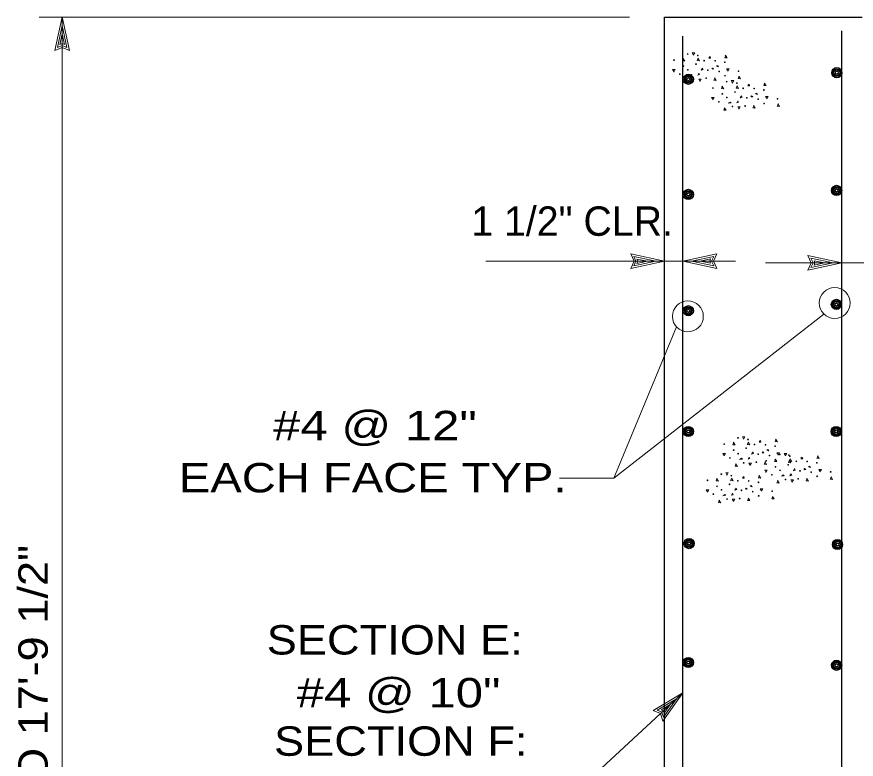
# Model space of a CAD drawing. Extents: x -28.1 to 13.9, y -16.1 to 13.9.
# Drawn here: x -10.389 to -6.817, y -5.87 to -2.71 of the extents above; entities that cross this region are included whole.
import ezdxf
from ezdxf.enums import TextEntityAlignment as Align

# ---------------------------------------------------------------- set-up
doc = ezdxf.new("R2010")
doc.units = 0
doc.header["$LTSCALE"] = 0.05
doc.layers.add('1', color=7, linetype='Continuous', lineweight=13)
doc.layers.add('2', color=7, linetype='Continuous', lineweight=13)

msp = doc.modelspace()

# ---------------------------------------------------------------- linework, layer by layer
at = {"layer": '1'}
for p, q in [((-7.78204, -2.71131), (-10.29304, -2.71131)), ((-10.19604, -2.71031), (-10.22704, -2.85431)), ((-10.19604, -2.71031), (-10.16504, -2.85431)), ((-10.19604, -2.74731), (-10.21604, -2.84131)), ((-10.19604, -2.74731), (-10.17604, -2.84131)), ((-10.19604, -2.78331), (-10.20504, -2.82831)), ((-10.19604, -2.78331), (-10.18604, -2.82831)), ((-10.19604, -2.83231), (-10.21604, -2.84131)), ((-10.19604, -2.82431), (-10.20504, -2.82831)), ((-10.18604, -2.82831), (-10.19604, -2.82431)), ((-10.17604, -2.84131), (-10.19604, -2.83231)), ((-7.63204, -3.75031), (-7.77604, -3.71931)), ((-7.63204, -3.75031), (-7.77604, -3.78131)), ((-7.66904, -3.75031), (-7.76304, -3.73031)), ((-7.75404, -3.75031), (-7.76304, -3.73031)), ((-7.66904, -3.75031), (-7.76304, -3.77031)), ((-7.76304, -3.77031), (-7.75404, -3.75031)), ((-7.70504, -3.75031), (-7.75004, -3.74131)), ((-7.74604, -3.75031), (-7.75004, -3.74131)), ((-7.70504, -3.75031), (-7.75004, -3.76031)), ((-7.75004, -3.76031), (-7.74604, -3.75031)), ((-7.55404, -3.75031), (-7.41004, -3.71931)), ((-7.55404, -3.75031), (-7.41004, -3.78131)), ((-7.51704, -3.75031), (-7.42304, -3.73031)), ((-7.51704, -3.75031), (-7.42304, -3.77031)), ((-7.48104, -3.75031), (-7.43604, -3.74031)), ((-7.48104, -3.75031), (-7.43604, -3.75931)), ((-7.43604, -3.74031), (-7.44004, -3.75031)), ((-7.44004, -3.75031), (-7.43604, -3.75931)), ((-7.42304, -3.73031), (-7.43204, -3.75031)), ((-7.43204, -3.75031), (-7.42304, -3.77031)), ((-6.87804, -3.75731), (-7.02204, -3.72631)), ((-6.91504, -3.75731), (-7.00904, -3.73731)), ((-7.00004, -3.75731), (-7.00904, -3.73731)), ((-6.95104, -3.75731), (-6.99604, -3.74831)), ((-6.99204, -3.75731), (-6.99604, -3.74831)), ((-6.87804, -3.75731), (-7.02204, -3.78831)), ((-6.91504, -3.75731), (-7.00904, -3.77731)), ((-7.00904, -3.77731), (-7.00004, -3.75731)), ((-6.95104, -3.75731), (-6.99604, -3.76731)), ((-6.99604, -3.76731), (-6.99204, -3.75731)), ((-7.84804, -4.67431), (-6.95404, -3.97531)), ((-7.55404, -5.58731), (-7.68104, -5.66231)), ((-7.58104, -5.61231), (-7.66404, -5.66131)), ((-7.60804, -5.63731), (-7.64704, -5.66031)), ((-7.58104, -5.61231), (-7.63704, -5.69131)), ((-7.60804, -5.63731), (-7.63404, -5.67431)), ((-7.64404, -5.67031), (-7.66404, -5.66131)), ((-7.63804, -5.66431), (-7.64704, -5.66031)), ((-7.63704, -5.69131), (-7.64404, -5.67031)), ((-7.63404, -5.67431), (-7.63804, -5.66431))]:
    msp.add_line(p, q, dxfattribs=at)
at = {"layer": '1', "lineweight": 25}
for p, q in [((-7.63204, -10.78531), (-7.63204, -2.71131)), ((-7.63204, -2.71131), (-6.79104, -2.71131)), ((-6.87804, -10.71531), (-6.87804, -2.77031)), ((-7.55404, -10.70931), (-7.55404, -2.79231))]:
    msp.add_line(p, q, dxfattribs=at)
at = {"layer": '1'}
for points in [[(-10.19604, -11.70431), (-10.19604, -9.90431), (-10.19604, -2.71031)], [(-10.16504, -2.85431), (-10.19604, -2.84031), (-10.22704, -2.85431)], [(-8.39304, -3.75031), (-7.63204, -3.75031), (-7.55404, -3.75031), (-7.33004, -3.75031)], [(-7.77604, -3.78131), (-7.76204, -3.75031), (-7.77604, -3.71931)], [(-7.41004, -3.71931), (-7.42404, -3.75031), (-7.41004, -3.78131)], [(-7.02204, -3.78831), (-7.00804, -3.75731), (-7.02204, -3.72631)], [(-7.20204, -3.75731), (-6.87804, -3.75731), (-6.79104, -3.75731), (-6.26604, -3.75731)], [(-8.07904, -4.67431), (-7.84804, -4.67431), (-7.58204, -4.02931)], [(-8.29204, -6.04931), (-8.05404, -6.04931), (-7.55404, -5.58731), (-7.63904, -5.70731)], [(-7.63904, -5.70731), (-7.64904, -5.67531), (-7.68104, -5.66231)]]:
    msp.add_lwpolyline(points, dxfattribs=at)
at = {"layer": '1', "lineweight": 25}
for centre, radius in [((-6.89899, -2.94823), 0.02168), ((-7.53099, -2.97623), 0.02168), ((-7.53099, -2.97623), 0.01681), ((-7.53099, -2.97623), 0.01233), ((-6.89899, -2.94823), 0.01681), ((-6.89899, -2.94823), 0.01233), ((-6.89899, -2.94823), 0.00623), ((-7.53099, -2.97623), 0.00623), ((-6.89999, -3.44923), 0.02168), ((-7.53099, -3.46623), 0.02168), ((-7.53099, -3.46623), 0.01681), ((-7.53099, -3.46623), 0.01233), ((-7.53099, -3.46623), 0.00623), ((-6.89999, -3.44923), 0.01681), ((-6.89999, -3.44923), 0.01233), ((-6.89999, -3.44923), 0.00623), ((-6.90099, -3.93423), 0.02168), ((-6.90099, -3.93423), 0.01681), ((-6.90099, -3.93423), 0.01233), ((-6.90099, -3.93423), 0.00623), ((-7.53099, -3.96123), 0.02168), ((-7.53099, -3.96123), 0.01681), ((-7.53099, -3.96123), 0.01233), ((-7.53099, -3.96123), 0.00623), ((-7.53099, -4.47523), 0.02168), ((-7.53099, -4.47523), 0.01681), ((-7.53099, -4.47523), 0.01233), ((-6.90199, -4.47523), 0.02168), ((-6.90199, -4.47523), 0.01681), ((-6.90199, -4.47523), 0.01233), ((-7.53099, -4.47523), 0.00623), ((-6.90199, -4.47523), 0.00623), ((-7.52799, -4.95223), 0.02168), ((-7.52799, -4.95223), 0.01681), ((-7.52799, -4.95223), 0.01233), ((-7.52799, -4.95223), 0.00623), ((-6.89599, -4.95623), 0.02168), ((-6.89599, -4.95623), 0.01681), ((-6.89599, -4.95623), 0.01233), ((-6.89599, -4.95623), 0.00623), ((-7.53099, -5.45823), 0.02168), ((-7.53099, -5.45823), 0.01681), ((-7.53099, -5.45823), 0.01233), ((-7.53099, -5.45823), 0.00623), ((-6.89999, -5.47023), 0.02168), ((-6.89999, -5.47023), 0.01681), ((-6.89999, -5.47023), 0.01233), ((-6.89999, -5.47023), 0.00623)]:
    msp.add_circle(centre, radius, dxfattribs=at)
at = {"layer": '1'}
for centre in [(-6.90804, -3.92831), (-7.53304, -3.98531)]:
    msp.add_circle(centre, 0.0658, dxfattribs=at)
at = {"layer": '2'}
for p, q in [((-7.44404, -2.88431), (-7.43804, -2.87931)), ((-7.27804, -3.00231), (-7.27204, -2.99731)), ((-7.23004, -4.51831), (-7.22404, -4.51331)), ((-7.05204, -4.58931), (-7.04604, -4.58431)), ((-7.30104, -4.67231), (-7.29504, -4.66731))]:
    msp.add_line(p, q, dxfattribs=at)
for points in [[(-7.55104, -2.88731), (-7.55604, -2.89731), (-7.54604, -2.89831), (-7.55404, -2.88731)], [(-7.51004, -2.87231), (-7.51504, -2.86331), (-7.50404, -2.86331), (-7.51004, -2.87431)], [(-7.48904, -2.88631), (-7.49404, -2.89631), (-7.48304, -2.89731), (-7.49104, -2.88631)], [(-7.43804, -2.87931), (-7.43604, -2.88631), (-7.44404, -2.88631)], [(-7.37104, -2.87431), (-7.37604, -2.88431), (-7.36604, -2.88531), (-7.37404, -2.87431)], [(-7.43104, -2.93231), (-7.42804, -2.92831), (-7.42304, -2.93231), (-7.43004, -2.93331)], [(-7.41104, -2.91931), (-7.40604, -2.91731), (-7.40304, -2.92331), (-7.41104, -2.92031)], [(-7.59304, -2.94331), (-7.59804, -2.93531), (-7.58704, -2.93531), (-7.59304, -2.94531)], [(-7.52404, -2.95831), (-7.51904, -2.95531), (-7.51504, -2.95831), (-7.52704, -2.96031)], [(-7.36304, -2.93931), (-7.36804, -2.93131), (-7.35704, -2.93131), (-7.36304, -2.94131)], [(-7.31404, -2.96331), (-7.31904, -2.97331), (-7.30904, -2.97431), (-7.31604, -2.96331)], [(-7.54104, -2.97931), (-7.54604, -2.98931), (-7.53604, -2.99031), (-7.54404, -2.97931)], [(-7.48204, -2.98431), (-7.48704, -2.97531), (-7.47604, -2.97531), (-7.48204, -2.98531)], [(-7.41704, -2.97031), (-7.42204, -2.98031), (-7.41204, -2.98131), (-7.42004, -2.97031)], [(-7.34404, -2.99031), (-7.34904, -2.98131), (-7.33804, -2.98131), (-7.34404, -2.99231)], [(-7.27204, -2.99731), (-7.27004, -3.00431), (-7.27804, -3.00431)], [(-7.20504, -2.99231), (-7.21004, -3.00231), (-7.20004, -3.00331), (-7.20804, -2.99231)], [(-7.38504, -3.00531), (-7.39004, -3.01531), (-7.38004, -3.01631), (-7.38804, -3.00531)], [(-7.32304, -3.00431), (-7.32804, -3.01431), (-7.31704, -3.01531), (-7.32504, -3.00431)], [(-7.24504, -3.03731), (-7.24004, -3.03531), (-7.23704, -3.04131), (-7.24504, -3.03831)], [(-7.42704, -3.06131), (-7.43204, -3.05331), (-7.42104, -3.05331), (-7.42704, -3.06331)], [(-7.26504, -3.05031), (-7.26204, -3.04631), (-7.25704, -3.05031), (-7.26404, -3.05131)], [(-7.19704, -3.05731), (-7.20204, -3.04931), (-7.19104, -3.04931), (-7.19704, -3.05931)], [(-7.37504, -3.09731), (-7.38004, -3.10731), (-7.37004, -3.10831), (-7.37804, -3.09731)], [(-7.35804, -3.07631), (-7.35304, -3.07331), (-7.34904, -3.07631), (-7.36104, -3.07831)], [(-7.31604, -3.10231), (-7.32104, -3.09331), (-7.31004, -3.09331), (-7.31604, -3.10331)], [(-7.25104, -3.08831), (-7.25604, -3.09831), (-7.24604, -3.09931), (-7.25404, -3.08831)], [(-7.14804, -3.08131), (-7.15304, -3.09131), (-7.14304, -3.09231), (-7.15004, -3.08131)], [(-7.29604, -4.50631), (-7.30104, -4.49731), (-7.29004, -4.49731), (-7.29604, -4.50831)], [(-7.33704, -4.52131), (-7.34204, -4.53131), (-7.33204, -4.53231), (-7.34004, -4.52131)], [(-7.27504, -4.52031), (-7.28004, -4.53031), (-7.26904, -4.53131), (-7.27704, -4.52031)], [(-7.22404, -4.51331), (-7.22204, -4.52031), (-7.23004, -4.52031)], [(-7.15704, -4.50831), (-7.16204, -4.51831), (-7.15204, -4.51931), (-7.16004, -4.50831)], [(-7.37904, -4.57731), (-7.38404, -4.56931), (-7.37304, -4.56931), (-7.37904, -4.57931)], [(-7.21704, -4.56631), (-7.21404, -4.56231), (-7.20904, -4.56631), (-7.21604, -4.56731)], [(-7.19704, -4.55331), (-7.19204, -4.55131), (-7.18904, -4.55731), (-7.19704, -4.55431)], [(-7.14904, -4.57331), (-7.15404, -4.56531), (-7.14304, -4.56531), (-7.14904, -4.57531)], [(-7.11804, -4.57731), (-7.12304, -4.56831), (-7.11204, -4.56831), (-7.11804, -4.57931)], [(-7.31004, -4.59231), (-7.30504, -4.58931), (-7.30104, -4.59231), (-7.31304, -4.59431)], [(-7.20304, -4.60431), (-7.20804, -4.61431), (-7.19804, -4.61531), (-7.20604, -4.60431)], [(-7.15904, -4.59231), (-7.16404, -4.60231), (-7.15404, -4.60331), (-7.16204, -4.59231)], [(-7.10004, -4.59731), (-7.10504, -4.60731), (-7.09504, -4.60831), (-7.10204, -4.59731)], [(-7.09704, -4.59131), (-7.10204, -4.60131), (-7.09104, -4.60231), (-7.09904, -4.59131)], [(-7.04604, -4.58431), (-7.04404, -4.59131), (-7.05204, -4.59131)], [(-6.97904, -4.57931), (-6.98404, -4.58931), (-6.97404, -4.59031), (-6.98204, -4.57931)], [(-7.32704, -4.61331), (-7.33204, -4.62331), (-7.32204, -4.62431), (-7.33004, -4.61331)], [(-7.26804, -4.61831), (-7.27304, -4.60931), (-7.26204, -4.60931), (-7.26804, -4.61931)], [(-7.20104, -4.64831), (-7.20604, -4.64031), (-7.19504, -4.64031), (-7.20104, -4.65031)], [(-7.03904, -4.63731), (-7.03604, -4.63331), (-7.03104, -4.63731), (-7.03804, -4.63831)], [(-7.01904, -4.62431), (-7.01404, -4.62231), (-7.01104, -4.62831), (-7.01904, -4.62531)], [(-6.97104, -4.64431), (-6.97604, -4.63631), (-6.96504, -4.63631), (-6.97104, -4.64631)], [(-7.40804, -4.67531), (-7.41304, -4.68531), (-7.40304, -4.68631), (-7.41104, -4.67531)], [(-7.36704, -4.66031), (-7.37204, -4.65131), (-7.36104, -4.65131), (-7.36704, -4.66231)], [(-7.34604, -4.67431), (-7.35104, -4.68431), (-7.34004, -4.68531), (-7.34804, -4.67431)], [(-7.29504, -4.66731), (-7.29304, -4.67431), (-7.30104, -4.67431)], [(-7.22804, -4.66231), (-7.23304, -4.67231), (-7.22304, -4.67331), (-7.23104, -4.66231)], [(-7.13204, -4.66331), (-7.12704, -4.66031), (-7.12304, -4.66331), (-7.13504, -4.66531)], [(-7.02504, -4.67531), (-7.03004, -4.68531), (-7.02004, -4.68631), (-7.02804, -4.67531)], [(-6.92204, -4.66831), (-6.92704, -4.67831), (-6.91704, -4.67931), (-6.92404, -4.66831)], [(-7.26804, -4.70731), (-7.26304, -4.70531), (-7.26004, -4.71131), (-7.26804, -4.70831)], [(-7.14904, -4.68431), (-7.15404, -4.69431), (-7.14404, -4.69531), (-7.15204, -4.68431)], [(-7.09004, -4.68931), (-7.09504, -4.68031), (-7.08404, -4.68031), (-7.09004, -4.69031)], [(-7.45004, -4.73131), (-7.45504, -4.72331), (-7.44404, -4.72331), (-7.45004, -4.73331)], [(-7.38104, -4.74631), (-7.37604, -4.74331), (-7.37204, -4.74631), (-7.38404, -4.74831)], [(-7.28804, -4.72031), (-7.28504, -4.71631), (-7.28004, -4.72031), (-7.28704, -4.72131)], [(-7.22004, -4.72731), (-7.22504, -4.71931), (-7.21404, -4.71931), (-7.22004, -4.72931)], [(-7.39804, -4.76731), (-7.40304, -4.77731), (-7.39304, -4.77831), (-7.40104, -4.76731)], [(-7.33904, -4.77231), (-7.34404, -4.76331), (-7.33304, -4.76331), (-7.33904, -4.77331)], [(-7.27404, -4.75831), (-7.27904, -4.76831), (-7.26904, -4.76931), (-7.27704, -4.75831)], [(-7.17104, -4.75131), (-7.17604, -4.76131), (-7.16604, -4.76231), (-7.17304, -4.75131)]]:
    msp.add_lwpolyline(points, dxfattribs=at)
for points in [[(-7.47604, -2.93731), (-7.47104, -2.92831), (-7.46804, -2.93431)], [(-7.49104, -2.95831), (-7.48604, -2.95031), (-7.48304, -2.95631)], [(-7.32504, -3.07631), (-7.32004, -3.06831), (-7.31704, -3.07431)], [(-7.31004, -3.05531), (-7.30504, -3.04631), (-7.30204, -3.05231)], [(-7.26204, -4.57131), (-7.25704, -4.56231), (-7.25404, -4.56831)], [(-7.27704, -4.59231), (-7.27204, -4.58431), (-7.26904, -4.59031)], [(-7.08404, -4.64231), (-7.07904, -4.63331), (-7.07604, -4.63931)], [(-7.09904, -4.66331), (-7.09404, -4.65531), (-7.09104, -4.66131)], [(-7.34804, -4.74631), (-7.34304, -4.73831), (-7.34004, -4.74431)], [(-7.33304, -4.72531), (-7.32804, -4.71631), (-7.32504, -4.72231)]]:
    msp.add_lwpolyline(points, close=True, dxfattribs=at)
for centre in [(-7.53379, -2.86844), (-7.49104, -2.87519), (-7.59204, -2.89519), (-7.55229, -2.92044), (-7.49854, -2.91219), (-7.46329, -2.89694), (-7.41704, -2.89794), (-7.37579, -2.90369), (-7.56754, -2.95419), (-7.53304, -2.93569), (-7.44804, -2.93744), (-7.40004, -2.94319), (-7.37479, -2.96094), (-7.31754, -2.94144), (-7.50954, -2.97444), (-7.45554, -2.97194), (-7.36779, -2.98644), (-7.32504, -2.99319), (-7.42604, -3.01319), (-7.33254, -3.03019), (-7.29729, -3.01494), (-7.25104, -3.01594), (-7.20979, -3.02169), (-7.40154, -3.07219), (-7.38629, -3.03844), (-7.36704, -3.05369), (-7.28204, -3.05544), (-7.23404, -3.06119), (-7.15154, -3.05944), (-7.34354, -3.09244), (-7.28954, -3.08994), (-7.20879, -3.07894), (-7.37804, -4.52919), (-7.31979, -4.50244), (-7.27704, -4.50919), (-7.24929, -4.53094), (-7.20304, -4.53194), (-7.16179, -4.53769), (-7.33829, -4.55444), (-7.31904, -4.56969), (-7.28454, -4.54619), (-7.23404, -4.57144), (-7.14179, -4.57344), (-7.35354, -4.58819), (-7.29554, -4.60844), (-7.24154, -4.60594), (-7.20004, -4.60019), (-7.18604, -4.57719), (-7.16079, -4.59494), (-7.10354, -4.57544), (-7.09904, -4.58019), (-7.07129, -4.60194), (-7.02504, -4.60294), (-6.98379, -4.60869), (-7.16029, -4.62544), (-7.14104, -4.64069), (-7.10654, -4.61719), (-7.05604, -4.64244), (-7.39079, -4.65644), (-7.34804, -4.66319), (-7.17554, -4.65919), (-7.11754, -4.67944), (-7.06354, -4.67694), (-7.00804, -4.64819), (-6.98279, -4.66594), (-6.92554, -4.64644), (-7.44904, -4.68319), (-7.40929, -4.70844), (-7.35554, -4.70019), (-7.32029, -4.68494), (-7.27404, -4.68594), (-7.23279, -4.69169), (-7.42454, -4.74219), (-7.39004, -4.72369), (-7.30504, -4.72544), (-7.25704, -4.73119), (-7.23179, -4.74894), (-7.17454, -4.72944), (-7.36654, -4.76244), (-7.31254, -4.75994)]:
    msp.add_circle(centre, 0.00162, dxfattribs=at)

# ---------------------------------------------------------------- texts
at = {"layer": '1'}
msp.add_text('1 1/2" CLR.', height=0.125, dxfattribs=at).set_placement((-7.59644, -3.64231), align=Align.RIGHT)
for s, width, p in [('#4 @ 12"', 1.25, (-8.86448, -4.51231)), ('EACH FACE TYP.', 1.2, (-8.87414, -4.73431)), ('SECTION E:', 1.15, (-8.78058, -5.42431)), ('#4 @ 10"', 1.25, (-8.76398, -5.64931)), ('SECTION F:', 1.15, (-8.75458, -5.85531))]:
    msp.add_text(s, height=0.125, dxfattribs=dict(at, width=width)).set_placement(p, align=Align.CENTER)
at = {"layer": '1', "width": 1.15}
msp.add_text('VARIES 6" TO 17\'-9 1/2"', height=0.125, rotation=90, dxfattribs=at).set_placement((-10.25704, -6.01675), align=Align.CENTER)

doc.saveas('drawing.dxf')
